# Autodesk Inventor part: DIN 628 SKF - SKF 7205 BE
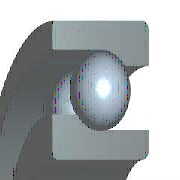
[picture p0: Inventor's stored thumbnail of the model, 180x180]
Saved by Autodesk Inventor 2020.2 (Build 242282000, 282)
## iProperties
IsCustomPart: 0
Manager: www.cadconsulting.pl
Company: Fabian Stasiak CAD Consulting
Created: 2014-02
Part Number: DIN 628 SKF - SKF 7205 BE
Material: Stal, miękka
Description: Łożyska toczne kulkowe skośne jednorzędowe SKF
Document SubType Name: Modeling
Standard: DIN 628 SKF
Designer: F.Stasiak
Standards Organization: DIN
Language: pl-PL
Size Designation: SKF 7205 BE
Categories: <MemberInstance><Categories><Category DisplayName="Części wałów" InternalName="7f7aeb1f-a693-4053-b835-cee3144e0d98" Mnemonic="SHFT"><Category DisplayName="Łoży
Density: 7.85 g/cm^3
Appearance: Częściowo polerowana
Catalog Web Link: www.expertbooks.pl
Author: F.Stasiak
Subject: Zbiór ćwiczeń. Autodesk Inventor 2020. Kurs Professional
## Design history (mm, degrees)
node "WorkPlane1"
workplane "Work Plane2"
node "WorkPlane2"
node "WorkPoint1"
node "WorkPoint3"
node "WorkPoint2"
node "WorkAxis1"
node "Szkic7"
workaxis "Work Axis2"
pattern_circular "SzykBiegunowy1" dims angle "d18" = 360 deg
body "Solid1"
node "Szkic1"
node "Szkic2"
node "Szkic3"
revolve "Obrót1" stored, may be unused: angle "d7" = 360 deg
revolve "Obrót2" stored, may be unused: angle "d12" = 360 deg
revolve "Obrót3" stored, may be unused: angle "d15" = 360 deg
fillet "Zaokrąglenie1" dims "d19" = 0.6 (= r1)
fillet "Zaokrąglenie2" dims "d20" = 1 (= r)
sketch "Szkic4"
  geometry: L1 (26, 0)-(12.5, 0); L2 (26, 15)-(26, 0); L3 (12.5, 15)-(26, 15); L4 (12.5, 0)-(12.5, 15); L5 (0, -3.737)-(0, 15.931); L6 (0, -3.737)-(0, 15.931); L7 (0, -7.671)-(0, 19.865) reference; L8 (-4.7, 0)-(28.2, 0) reference
  constraints: 12 end point, 3 vertical, 2 collinear, 2 horizontal
  dimensions: "d2" = 12.5 horizontal distance of L3.start L5.end (= 0.5 x Diam); "d4" = 26 horizontal distance of L2.start L5.end (= 0.5 x DD); "d6" = 15 distance of L1.end L3.start (= B)
sketch "Szkic5"
  geometry: L1 (23.3, 15)-(16.82, 15); L2 (23.3, 7.5)-(23.3, 15); L3 (21.68, 0)-(21.68, 4.26); L4 (15.2, 0)-(21.68, 0); L5 (15.2, 7.5)-(15.2, 0); L6 (16.82, 15)-(16.82, 10.74); L7 (26, 0)-(-26, 0) reference; L8 (26, 15)-(-26, 15) reference; L9 (0, 40.963)-(0, -26.963); L10 (0, -40.549)-(0, 54.549) reference; A1 r 4.05 centre (19.25, 7.5) between (21.68, 4.26) and (23.3, 7.5); A2 r 4.05 centre (19.25, 7.5) between (16.82, 10.74) and (15.2, 7.5); A3 r 4.05 centre (19.25, 7.5) between (23.3, 7.5) and (16.82, 10.74)
  constraints: 14 end point, 7 point on circle, 4 vertical, 3 centre point, 3 collinear, 2 horizontal, 2 tangent, 1 coincident, 1 concentric
  dimensions: "d9" = 7.5 vertical distance of A2.centre L3.start (= 0.5 x B); "d11" = 8.1 diameter of A3 (= msp_mdtdk); "d21" = 38.5 diameter of A1.centre L9 (= msp_mdtds); "d22" = 33.64 diameter of L6 L9 (= msp_md); "d23" = 43.36 diameter of L3 L9 (= msp_vd)
sketch "Szkic6"
  geometry: L1 (19.25, 3.45)-(19.25, 11.55); L2 (19.25, 15.675)-(19.25, -0.513); L3 (26, 0)-(-26, 0) reference; L4 (19.25, 15.675)-(19.25, -0.513); L5 (23.3, 7.5)-(-23.3, 7.5) reference; A1 r 4.05 centre (19.25, 7.5) between (19.25, 3.45) and (19.25, 11.55); A2 r 4.05 centre (19.25, 7.5) between (16.82, 10.74) and (15.2, 7.5) reference
  constraints: 6 end point, 4 point on line, 2 point on circle, 1 centre point, 1 concentric, 1 vertical
  dimensions: "d14" = 4.05 radius of A1 (= 0.5 x msp_mdtdk)
other parameters: "Diam" = 25 [user parameter; used in 3 equation terms], "DD" = 52 [user parameter; used in 3 equation terms], "B" = 15 [user parameter; used in 3 equation terms], "r" = 1 [user parameter; used in 1 equation term], "msp_mdtdk" = 8.1 (= -0.3 x Diam + 0.3 x DD) [user parameter; used in 5 equation terms], "msp_mdtds" = 38.5 (= 0.5 x DD + 0.5 x Diam) [user parameter; used in 4 equation terms], "msp_md" = 33.64 (= msp_mdtds - 0.6 x msp_mdtdk) [user parameter; used in 1 equation term], "msp_vd" = 43.36 (= msp_mdtds + 0.6 x msp_mdtdk) [user parameter; used in 1 equation term], "r1" = 0.6 [user parameter; used in 1 equation term], "d0" = -15 (computed from B), "d3" = 23.5 (derived), "d5" = 14 (derived), "d8" = 7 (derived), "d10" = 8.1 (derived), "d13" = 4.05 (derived), "d26" = 0, "d27" = 0, "d28" = 0, "d29" = 0, "d30" = 0
